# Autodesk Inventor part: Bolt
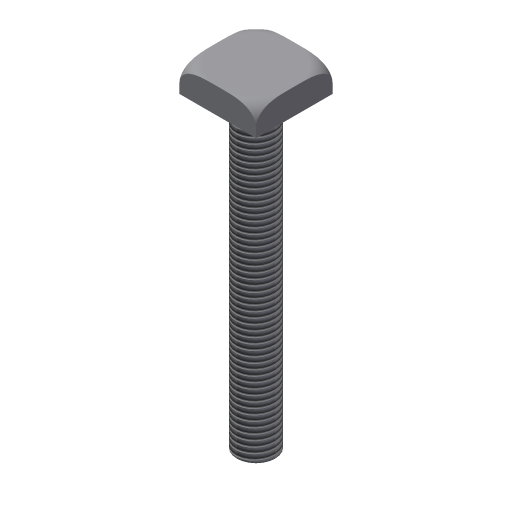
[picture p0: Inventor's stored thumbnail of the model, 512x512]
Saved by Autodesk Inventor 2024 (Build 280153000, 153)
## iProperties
Created: 2009-04
Part Number: Bolt
Document SubType Name: Modeling
Designer: Sham
Density: 1 g/cm^3
Material: Generic
Appearance: Default
Author: Sham
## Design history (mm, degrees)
sketch "Sketch1"
  geometry: L1 (-12, 12)-(12, 12); L2 (12, 12)-(12, -12); L3 (12, -12)-(-12, -12); L4 (-12, -12)-(-12, 12); 1 further point
  constraints: 8 end point, 2 parallel, 2 perpendicular, 1 horizontal, 1 other
  dimensions: "d0" = 24 distance of L1.start L1.end; "d1" = 12 distance from line of L2 point (0, 0); "d2" = 12 distance from line of L1 point (0, 0)
extrude "Extrusion1" new body sketch "Sketch1" distance "d3" = 8; taper "d4" = 0 deg
sketch "Sketch2"
  geometry: C1 r 6 at (0, 0)
  constraints: 1 centre point
  dimensions: "d5" = 12 diameter of C1
extrude "Extrusion2" join sketch "Sketch2" distance "d6" = 96; taper "d7" = 0 deg
workpoint "Work Point1"
workplane "Work Plane1"
sketch "Sketch3"
  geometry: L1 (33.941, 5)-(33.941, 6); L2 (28.941, 0)-(28.405, 0); L3 (16.971, 125.007)-(16.971, -22.043) reference; A1 r 5 centre (28.941, 5) between (28.941, 0) and (33.941, 5); 1 further point
  constraints: 4 end point, 2 point on circle, 2 point on line, 2 tangent, 1 centre point, 1 perpendicular
  dimensions: "d10" = 5 radius of A1
revolve "Revolution1" sketch "Sketch3" stored, may be unused: angle "d12" = 90 deg
thread "Thread1" dims "d13" = 96, "d14" = 0
body "Solid1"
other parameters: "d11" = 90 deg
